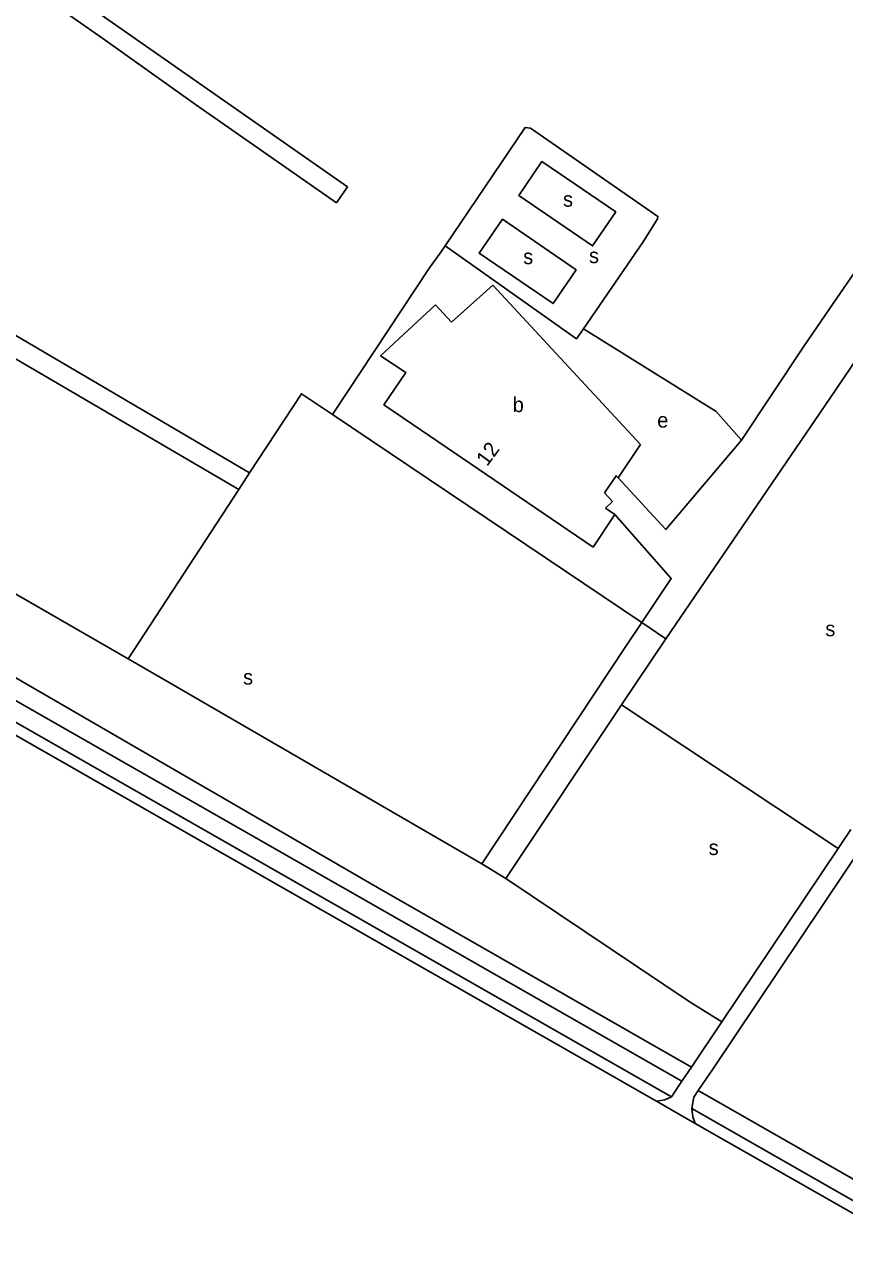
# Model space of a CAD drawing. Extents: x 157155 to 159285, y 385001 to 386651.
# Drawn here: x 158344.8 to 158563.8, y 385278.4 to 385603.8 of the extents above; entities that cross this region are included whole.
import ezdxf

# ---------------------------------------------------------------- set-up
doc = ezdxf.new("R2010")
doc.units = 0
for name, color, linetype in [('BLT_Basislijn', 7, 'Continuous'), ('BLT_Bebouwing', 7, 'Continuous'), ('BLT_Centroide', 7, 'Continuous'), ('BLT_Huisnummer', 7, 'Continuous'), ('BLT_Vlakafsluiter', 7, 'Continuous')]:
    doc.layers.add(name, color=color, linetype=linetype)

msp = doc.modelspace()

# ---------------------------------------------------------------- linework, layer by layer
at = {"layer": 'BLT_Basislijn'}
for p, q in [((158061.86, 385583.4), (158520.35, 385321.48)), ((158059.85, 385578.79), (158517.55, 385317.32)), ((158059.74, 385575.4), (158513.56, 385316.15)), ((158431.03, 385560.34), (158428.12, 385556.08)), ((158452.97, 385538.71), (158455.78, 385542.61)), ((158559.8, 385503.88), (158572.92, 385523.29)), ((158552.82, 385517.63), (158536.23, 385492.68)), ((158404.93, 385483.98), (158402.02, 385479.52)), ((158402.02, 385479.52), (158372.47, 385434.35)), ((158319.99, 385442.22), (158439.03, 385373.25)), ((158509.64, 385444), (158505.29, 385437.51)), ((158516.05, 385439.65), (158509.64, 385444)), ((158466.93, 385379.55), (158505.29, 385437.51)), ((158372.47, 385434.35), (158379.46, 385430.33)), ((158466.93, 385379.55), (158379.46, 385430.33)), ((158504.23, 385422.02), (158562.09, 385383.69)), ((158565.46, 385388.72), (158562.09, 385383.69)), ((158569.62, 385385.93), (158528.73, 385325)), ((158562.09, 385383.69), (158530.99, 385337.35)), ((158466.93, 385379.55), (158473.35, 385375.63)), ((158439.03, 385373.25), (158522.86, 385325.23)), ((158530.99, 385337.35), (158522.86, 385325.23)), ((158522.86, 385325.23), (158520.35, 385321.48)), ((158520.35, 385321.48), (158517.55, 385317.32)), ((158524.7, 385319), (158658.07, 385242.8)), ((158523.9, 385310.24), (158946.21, 385068.98))]:
    msp.add_line(p, q, dxfattribs=at)
for points in [[(158402.08, 385745.85), (158374.16, 385765.71), (158369.08, 385768.96), (158368.6, 385768.88), (158367.01, 385766.57), (158322.72, 385700), (158307.24, 385677.11), (158293.76, 385656.59), (158293.8, 385656.25), (158431.03, 385560.34)], [(158428.12, 385556.08), (158390.45, 385582.34), (158365.78, 385599.95), (158289.97, 385652.86), (158288.7, 385653.5), (158241.27, 385580.62), (158241.42, 385580.02), (158404.93, 385483.98)], [(158080.36, 385602.55), (158285.26, 385483.93), (158335.7, 385455.5), (158372.47, 385434.35)], [(158552.82, 385517.63), (158559.78, 385527.78), (158608.05, 385598.05), (158608.71, 385600.34), (158607.67, 385602.42), (158605.06, 385604.69)], [(158207.94, 385593.09), (158402.02, 385479.52)], [(158457.11, 385544.57), (158478.46, 385576.2), (158479.95, 385576.01), (158481.38, 385575.05), (158513.92, 385552.45), (158513.85, 385551.78), (158510.02, 385545.72), (158494.06, 385522.44)], [(158502.67, 385553.66), (158482.96, 385567.12), (158476.78, 385558.06), (158496.49, 385544.6), (158502.67, 385553.66)], [(158492.14, 385538.24), (158472.43, 385551.69), (158466.24, 385542.64), (158485.95, 385529.18), (158492.14, 385538.24)], [(158455.78, 385542.61), (158457.11, 385544.57)], [(158494.06, 385522.44), (158492.19, 385519.79), (158457.11, 385544.57)], [(158452.97, 385538.71), (158427.02, 385499.58)], [(158536.23, 385492.68), (158529.44, 385500.37), (158494.06, 385522.44)], [(158427.02, 385499.58), (158418.77, 385505.12), (158404.93, 385483.98)], [(158559.8, 385503.88), (158516.05, 385439.65)], [(158509.64, 385444), (158427.02, 385499.58)], [(158503.29, 385482.64), (158516.02, 385468.84), (158536.23, 385492.68)], [(158509.64, 385444), (158517.49, 385455.8), (158502.45, 385472.82)], [(158516.05, 385439.65), (158504.23, 385422.02)], [(158504.23, 385422.02), (158473.35, 385375.63)], [(158473.35, 385375.63), (158522.55, 385342.65), (158530.99, 385337.35)], [(158528.73, 385325), (158524.7, 385319)], [(158524.7, 385319), (158523.5, 385317.21), (158522.97, 385314.23)], [(158517.55, 385317.32), (158515.76, 385316.53), (158513.56, 385316.15)], [(158523.9, 385310.24), (158523.27, 385311.98), (158522.97, 385314.23)], [(158522.97, 385314.23), (158948.8, 385070.96), (158946.21, 385068.98)]]:
    msp.add_lwpolyline(points, dxfattribs=at)
at = {"layer": 'BLT_Bebouwing'}
for p, q in [((158458.8, 385524.24), (158469.87, 385534.14)), ((158469.87, 385534.14), (158509.32, 385491.52)), ((158439.91, 385515.24), (158454.52, 385528.84)), ((158454.52, 385528.84), (158458.8, 385524.24)), ((158496.6, 385464.17), (158450.75, 385495.37)), ((158499.65, 385478.62), (158501.78, 385476.34)), ((158501.78, 385476.34), (158499.9, 385474.55))]:
    msp.add_line(p, q, dxfattribs=at)
for points in [[(158450.74, 385495.37), (158440.78, 385502.16), (158446.66, 385510.77), (158439.91, 385515.24)], [(158509.32, 385491.52), (158503.29, 385482.64)], [(158503.29, 385482.64), (158502.77, 385483.22), (158499.65, 385478.62)], [(158502.45, 385472.82), (158496.6, 385464.17)], [(158499.9, 385474.55), (158502.45, 385472.82)]]:
    msp.add_lwpolyline(points, dxfattribs=at)
at = {"layer": 'BLT_Vlakafsluiter'}
msp.add_line((158523.9, 385310.24), (158513.56, 385316.15), dxfattribs=at)

# ---------------------------------------------------------------- texts
at = {"layer": 'BLT_Centroide'}
for s, p in [('s', (158488.59, 385555.06)), ('s', (158495.53, 385539.99)), ('s', (158477.97, 385539.72)), ('b', (158475.16, 385500.2)), ('e', (158513.74, 385496.07)), ('s', (158558.62, 385440.35)), ('s', (158403.19, 385427.43)), ('s', (158527.47, 385381.91))]:
    msp.add_text(s, height=4, dxfattribs=at).set_placement(p)
at = {"layer": 'BLT_Huisnummer'}
msp.add_text('12', height=4, rotation=53.8185, dxfattribs=at).set_placement((158468.34, 385485.52))

doc.saveas('drawing.dxf')
